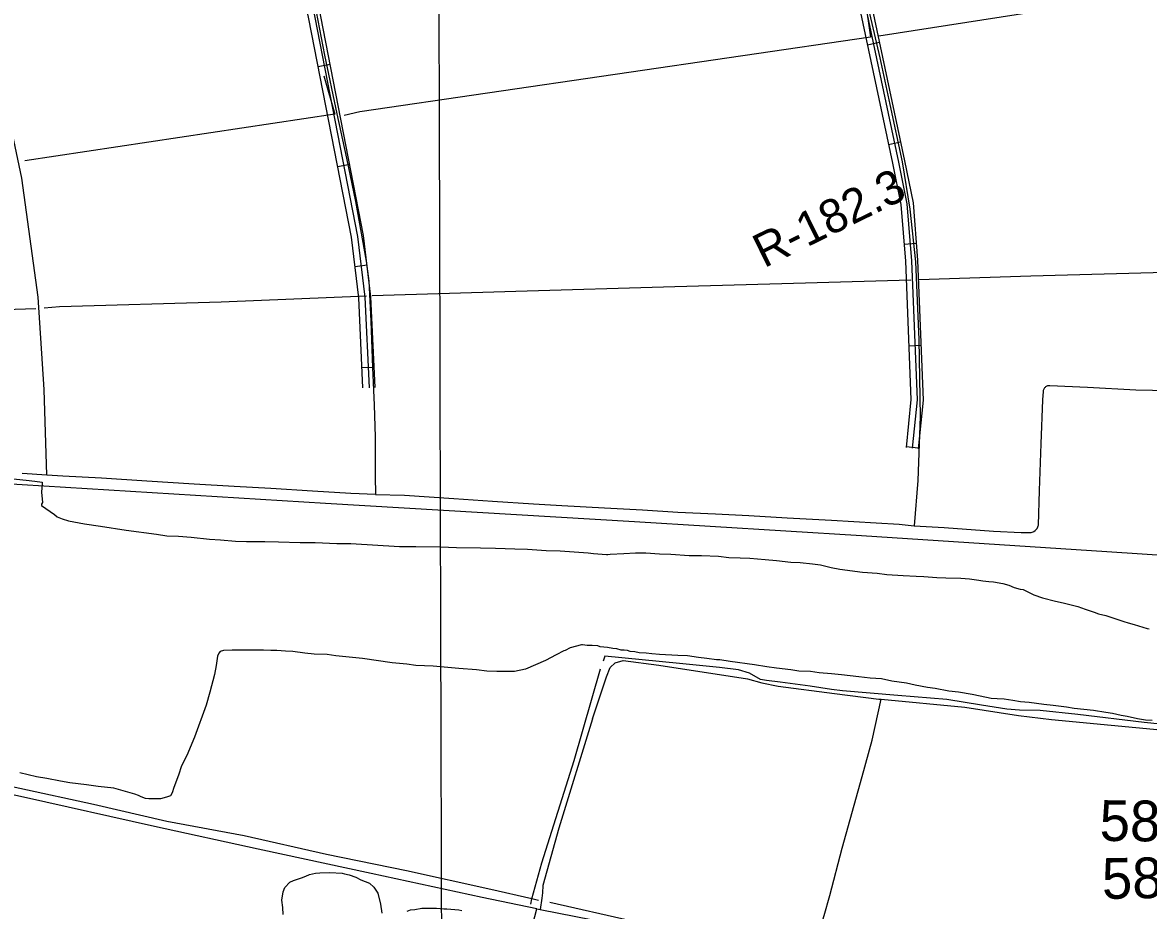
# Model space of a CAD drawing. Extents: x 3355724 to 3393621, y 594744 to 620174.
# Drawn here: x 3379882 to 3382643, y 602888 to 605066 of the extents above; entities that cross this region are included whole.
import ezdxf

# ---------------------------------------------------------------- set-up
doc = ezdxf.new("R2010")
doc.units = 0
for name, color, linetype in [('V-DTCH-CNTR', 7, 'Continuous'), ('V-GRID-MAJR', 7, 'Continuous'), ('V-RIVR-RANG-IDEN', 7, 'Continuous'), ('V-ROAD-CNTR', 7, 'Continuous'), ('V-SITE-VEGE', 7, 'Continuous'), ('V-SURV-IDEN', 7, 'Continuous'), ('V-TOPO-SHOR', 7, 'Continuous')]:
    doc.layers.add(name, color=color, linetype=linetype)

msp = doc.modelspace()

# ---------------------------------------------------------------- linework, layer by layer
at = {"layer": 'V-DTCH-CNTR'}
for points in [[(3381503.5, 606759.2), (3381522.8, 606700.6), (3381548.5, 606624.1), (3381574.1, 606534.7), (3381605.7, 606435.7), (3381639.6, 606329.6), (3381673.5, 606222.8), (3381714.9, 606091.5), (3381734.7, 606022.3), (3381744.1, 605992), (3381747.7, 605980.1), (3381756, 605959.5), (3381785.2, 605861.6), (3381812.4, 605764.8), (3381840.6, 605643.6), (3381868.7, 605519.6), (3381891.4, 605400.3), (3381918.5, 605268.6), (3381953.4, 605112.7), (3381984.3, 604979.8), (3382008.9, 604865.2), (3382038.7, 604724.1)], [(3379941.5, 603955.8), (3379935.5, 604166.2), (3379920.8, 604392.1), (3379880.2, 604684.5), (3379828.6, 604932.5), (3379746.8, 605265), (3379712.7, 605407.2), (3379660.4, 605620), (3379581.1, 605960.3), (3379555.8, 606069.7)], [(3380597.9, 605113.5), (3380622.9, 604986.4), (3380653.1, 604842.2), (3380676.5, 604733.4), (3380698.4, 604626.9), (3380724.7, 604481.1), (3380731.1, 604431.8), (3380735.8, 604333.4), (3380740.6, 604219.8), (3380744.5, 604127.2), (3380746.8, 604049.8), (3380747.2, 603953.4), (3380747.8, 603908.6), (3380687.5, 603911.1), (3380592.9, 603916.5), (3380491.4, 603922.7), (3380401.1, 603927.7), (3380302.7, 603933.9), (3380186.7, 603941.2), (3380075.8, 603948.1), (3379980.9, 603953.2), (3379941.5, 603955.8), (3379881.3, 603959.7)], [(3382038.7, 604724.1), (3382057.9, 604608.3), (3382071.6, 604479.2), (3382079.5, 604288.6), (3382083.4, 604099.6), (3382077.1, 603942.4), (3382068.2, 603831.9)], [(3380747.8, 603908.6), (3380819, 603906.6), (3380939.6, 603898.6), (3381034.2, 603892), (3381134.9, 603885.4), (3381204.2, 603881.4), (3381308.9, 603875.7), (3381402.2, 603871), (3381489, 603865.2), (3381581.6, 603861.3), (3381663.3, 603857), (3381756.7, 603851.5), (3381866, 603845), (3381975.4, 603838.9), (3382031.4, 603835.2), (3382068.2, 603831.9), (3382142.1, 603827.5), (3382263.2, 603818.7), (3382330.9, 603815.5), (3382351.1, 603814.8), (3382353.3, 603815), (3382355.5, 603815.3), (3382359.7, 603816.7), (3382361.6, 603817.6), (3382365.3, 603820.2), (3382368.3, 603823.3), (3382369.6, 603825.1), (3382371.7, 603829), (3382372.4, 603831.1), (3382372.9, 603833.2), (3382375.9, 603918), (3382379.3, 604032.8), (3382383.9, 604140.6), (3382385.4, 604161.2), (3382385.5, 604162.9), (3382385.7, 604164.6), (3382386.2, 604166.3), (3382386.9, 604167.8), (3382387.7, 604169.3), (3382388.7, 604170.7), (3382389.9, 604172), (3382391.2, 604173.1), (3382392.6, 604174.1), (3382394.2, 604174.8), (3382395.8, 604175.4), (3382397.4, 604175.8), (3382399.2, 604176), (3382400.9, 604176), (3382493.5, 604171.4), (3382611.8, 604164.9), (3382735.1, 604162.3)], [(3381279.3, 603358), (3381313.6, 603461.3), (3381323.1, 603483.8), (3381335.5, 603495.2), (3381355.1, 603501.1), (3381442.7, 603489.7), (3381659.4, 603456.2), (3381695.2, 603446.2), (3381734.5, 603438.3), (3381872.6, 603420.5), (3381982, 603406.6), (3381987.7, 603406.1), (3382192.2, 603387), (3382324, 603366.4), (3382404.7, 603356.3), (3382551.1, 603342.2), (3382672.3, 603331.2)], [(3381142.8, 602892.2), (3381008.8, 602919.8), (3380737.1, 602978.4), (3380459.9, 603038.4), (3380205.8, 603093.7), (3379885, 603165.7), (3379586, 603230.3), (3379241.4, 603304.7), (3378950.8, 603368.7), (3378694.7, 603425.1)], [(3381808.8, 602754.1), (3381824.3, 602799.8), (3381847.7, 602875.7), (3381861.8, 602924.9), (3381891.7, 603040.8), (3381941.1, 603216.4), (3381965.1, 603305.6), (3381987.7, 603406.1)], [(3381279.3, 603358), (3381197.5, 603090.3), (3381158.1, 602949.1), (3381157, 602931.5), (3381155.7, 602918.2), (3381151.7, 602890.4)], [(3381114.2, 602782.6), (3381142.8, 602892.2), (3381151.7, 602890.4), (3381451.5, 602831.2)]]:
    msp.add_lwpolyline(points, dxfattribs=at)
at = {"layer": 'V-GRID-MAJR'}
msp.add_spline([(3380917.6, 600183.6), (3380900.8, 606241.7), (3380884.1, 612302.9), (3380867.3, 618364.1), (3380867.3, 618367.2)], degree=3, dxfattribs=at)
at = {"layer": 'V-ROAD-CNTR'}
for p, q in [((3381982.9, 605017), (3381953.5, 605010.8)), ((3380606.9, 604958.1), (3380636.3, 604963.9)), ((3382034.6, 604772.4), (3382005.2, 604766.2)), ((3380654.9, 604712.8), (3380684.4, 604718.6)), ((3382073.5, 604524), (3382043.6, 604521.6)), ((3380697.4, 604467.7), (3380727.2, 604471.3)), ((3382085.1, 604273.6), (3382055.1, 604272.5)), ((3380714.5, 604219.5), (3380744.4, 604220.9)), ((3382078.5, 604022.2), (3382048.6, 604025.2))]:
    msp.add_line(p, q, dxfattribs=at)
for points in [[(3381502, 606748.4), (3381713.6, 606066.2), (3381758.7, 605978), (3381764.3, 605956.2), (3381798.1, 605818.6), (3382029.5, 604723.8), (3382050.7, 604621.5), (3382061.9, 604481.9), (3382075.3, 604140.5), (3382063.4, 604021.8)], [(3380383.6, 606126.5), (3380486.4, 605618.5), (3380598.7, 605078), (3380703.8, 604541.6), (3380721.4, 604392.2), (3380731.8, 604170.3)], [(3381774.4, 605976.9), (3381778.8, 605959.9), (3381812.7, 605821.9), (3382044.2, 604726.9), (3382065.6, 604623.6), (3382076.8, 604482.8), (3382090.3, 604140.1), (3382078.3, 604020.3)], [(3381744.9, 605971.1), (3381749.7, 605952.6), (3381783.4, 605815.2), (3382014.8, 604720.7), (3382035.9, 604619.4), (3382046.9, 604481), (3382060.3, 604141), (3382048.5, 604023.3)], [(3380746.8, 604171), (3380736.4, 604393.5), (3380718.6, 604544), (3380613.4, 605080.9), (3380500.6, 605623.7)], [(3380716.8, 604169.6), (3380706.5, 604391), (3380688.9, 604539.3), (3380584, 605075), (3380471.6, 605615.6)]]:
    msp.add_lwpolyline(points, dxfattribs=at)
at = {"layer": 'V-SITE-VEGE'}
for points in [[(3379852, 603947.9), (3379891.3, 603943.8), (3379912.5, 603940.7), (3379930.6, 603938.6), (3379930.6, 603936.5), (3379928.6, 603914.2), (3379930.8, 603888.7), (3379928.7, 603884.5), (3379928.7, 603881.3), (3379960.7, 603859.1), (3379967, 603853.9), (3379979.8, 603848.6), (3379994.7, 603843.4), (3380034, 603836.1), (3380073.3, 603831), (3380136, 603820.6), (3380210.4, 603811.4), (3380235.9, 603807.2), (3380264.5, 603806.3), (3380295.3, 603803.3), (3380341, 603799.2), (3380367.6, 603797.2), (3380404.7, 603794.2), (3380431.3, 603793.2), (3380475.9, 603793.4), (3380509.9, 603792.5), (3380562.9, 603790.6), (3380600.1, 603790.8), (3380653.2, 603787.8), (3380687.2, 603788), (3380806.1, 603781.1), (3380846.5, 603781.2), (3380907, 603780.4), (3380946.3, 603778.5), (3381004.7, 603777.7), (3381041.8, 603776.8), (3381089.6, 603774.9), (3381120.4, 603773.9), (3381166.1, 603770.9), (3381200.1, 603770), (3381269.1, 603765), (3381281.8, 603764), (3381313.7, 603761), (3381316.9, 603761), (3381323.3, 603762.1), (3381356.2, 603763.3), (3381384.8, 603765.5), (3381410.3, 603765.6), (3381444.3, 603762.6), (3381471.9, 603761.6), (3381516.5, 603758.7), (3381547.3, 603758.8)], [(3381547.3, 603758.8), (3381588.7, 603756.8), (3381614.2, 603753.8), (3381641.8, 603752.8), (3381665.2, 603751.9), (3381703.4, 603748.8), (3381731, 603746.8), (3381766.1, 603742.7), (3381788.4, 603741.8), (3381819.2, 603738.7), (3381838.3, 603735.6), (3381864.9, 603729.4), (3381886.1, 603725.2), (3381941.4, 603718), (3381977.5, 603715), (3382000.9, 603711.9), (3382041.2, 603710), (3382073.1, 603708), (3382092.2, 603707), (3382124, 603705), (3382146.3, 603704.1), (3382182.5, 603703.1), (3382203.7, 603701.1), (3382227.1, 603698), (3382236.6, 603697), (3382251.5, 603695), (3382263.2, 603693.9), (3382285.5, 603689.8), (3382300.4, 603685.6), (3382313.1, 603680.4), (3382328, 603676.2), (3382335.5, 603675.1), (3382341.8, 603672), (3382362.1, 603662.5), (3382383.3, 603655.2), (3382415.2, 603646.8), (3382433.3, 603642.7), (3382469.4, 603633.3), (3382487.5, 603627), (3382509.8, 603619.6), (3382520.5, 603615.4), (3382538.5, 603611.3), (3382550.2, 603607.1), (3382570.4, 603600.8), (3382582.1, 603596.6), (3382592.8, 603593.4), (3382607.6, 603589.3), (3382639.5, 603579.8), (3382644.8, 603578.8)], [(3380366.6, 603523.3), (3380363.5, 603519), (3380360.3, 603511.6), (3380357.2, 603489.3), (3380353.1, 603466.9), (3380341.6, 603423.4), (3380332.2, 603391.5), (3380303.8, 603312.8), (3380284.9, 603268.1), (3380272.3, 603242.6), (3380264.9, 603220.2), (3380253.4, 603189.4), (3380249.2, 603176.6), (3380245, 603169.2), (3380235.5, 603166), (3380220.6, 603161.7), (3380191.9, 603161.5), (3380183.4, 603162.6), (3380172.8, 603166.8), (3380166.4, 603169.9), (3380157.9, 603173.1), (3380129.2, 603181.4), (3380105.8, 603187.7), (3380067.6, 603191.8), (3380038.9, 603195.9), (3379998.5, 603201), (3379975.2, 603205.2), (3379942.2, 603211.4), (3379916.7, 603215.5), (3379875.3, 603226)], [(3382652.2, 603353.8), (3382635.2, 603354.7), (3382616.1, 603357.8), (3382590.6, 603364.1), (3382575.7, 603366.2), (3382554.4, 603371.4), (3382538.5, 603373.4), (3382507.7, 603378.6), (3382460.9, 603383.7), (3382441.8, 603386.8), (3382408.9, 603390.9), (3382386.6, 603392.9), (3382350.5, 603398.1), (3382329.2, 603400.1), (3382310.1, 603403.2), (3382288.8, 603406.3), (3382271.9, 603407.3), (3382257, 603408.3), (3382230.4, 603413.5), (3382210.2, 603417.7), (3382177.3, 603423.9), (3382152.9, 603425.9), (3382119.9, 603432.1), (3382100.8, 603435.2), (3382071, 603440.4), (3382049.8, 603445.6), (3382013.7, 603450.8), (3381988.2, 603456), (3381960.6, 603458), (3381932.9, 603461.1), (3381890.4, 603466.2), (3381866, 603468.2), (3381835.2, 603471.2), (3381814, 603474.3), (3381785.3, 603475.3), (3381766.2, 603478.4), (3381731.1, 603482.5), (3381706.7, 603485.6), (3381676.9, 603490.7), (3381658.9, 603492.8), (3381635.5, 603495.9), (3381617.4, 603499), (3381591.9, 603503.1), (3381583.4, 603503.1), (3381560.1, 603506.2), (3381539.9, 603508.2), (3381512.3, 603512.3), (3381488.9, 603513.3), (3381444.3, 603516.3), (3381425.2, 603517.2), (3381411.4, 603519.3), (3381394.4, 603520.3), (3381383.8, 603522.4), (3381372.1, 603523.4), (3381365.7, 603525.5), (3381357.2, 603526.5), (3381349.8, 603526.5), (3381339.1, 603529.6), (3381329.6, 603530.6), (3381316.8, 603532.7), (3381298.8, 603534.7), (3381292.4, 603536.8), (3381278.6, 603537.8), (3381266.9, 603537.8), (3381255.2, 603539.9), (3381253.1, 603539.9), (3381224.5, 603532.3), (3381212.8, 603525.9), (3381209.6, 603524.8), (3381190.6, 603515.2), (3381164.1, 603501.3), (3381115.3, 603479.8), (3381088.8, 603474.4), (3381045.3, 603474.2), (3381020.9, 603475.2), (3380995.4, 603478.2), (3380951.8, 603481.2), (3380925.3, 603484.3), (3380889.1, 603487.3), (3380846.7, 603489.3), (3380824.4, 603492.3), (3380788.2, 603495.4), (3380716, 603505.7), (3380650.1, 603512.8), (3380628.9, 603515.9), (3380597, 603516.8), (3380574.7, 603518.9), (3380545, 603523), (3380526.9, 603524), (3380505.7, 603526), (3380490.8, 603525.9), (3380472.8, 603526.9), (3380396.3, 603526.6), (3380375.1, 603525.4), (3380366.6, 603523.3)], [(3380521.2, 602878.4), (3380520.1, 602895.4), (3380517.9, 602913.4), (3380521, 602933.6), (3380525.2, 602944.3), (3380537.9, 602957.1), (3380546.4, 602961.3), (3380566.5, 602967.8), (3380577.1, 602972.1)], [(3380577.1, 602972.1), (3380585.6, 602976.4), (3380600.4, 602979.6), (3380611, 602980.7), (3380635.5, 602980.8), (3380666.3, 602979.9), (3380671.6, 602977.8), (3380683.3, 602975.7), (3380699.2, 602969.4), (3380712, 602963.1), (3380733.3, 602954.7), (3380743.9, 602945.2), (3380753.5, 602930.4), (3380760, 602903.9), (3380763.3, 602881.6)], [(3380824.9, 602886.1), (3380833.3, 602889.3), (3380844, 602890.4), (3380860.9, 602893.7), (3380897, 602893.8), (3380915.1, 602891.8), (3380922.5, 602891.8), (3380952.3, 602889.8), (3380959.7, 602887.8)]]:
    msp.add_lwpolyline(points, dxfattribs=at)
at = {"layer": 'V-TOPO-SHOR'}
msp.add_line((3381128.4, 602903.7), (3381130.8, 602916.3), dxfattribs=at)
for points in [[(3383156.7, 605227.5), (3383038.9, 605197.8), (3381981.7, 605033)], [(3381949.1, 605115.4), (3381961.1, 605030), (3380709.5, 604847), (3380671.2, 604838)], [(3380620.9, 604935.1), (3380647.6, 604840.9), (3379887.9, 604727)], [(3383382.6, 604479.8), (3383328.7, 604476.1), (3383078.9, 604471.6), (3382744.4, 604454.8), (3382354.2, 604443.7), (3382079.6, 604434.8)], [(3382059.9, 604433.8), (3381801.5, 604426.7), (3381481.5, 604417.6), (3381091.4, 604406.5), (3380739.7, 604395.6)], [(3380725.2, 604394.7), (3380369.3, 604380.3), (3379973.2, 604368.3), (3379935.5, 604365.6)], [(3379915, 604363.8), (3379583, 604352.9), (3379229.7, 604337.7), (3378804.5, 604323.9), (3378613.7, 604317.1)], [(3383444.9, 603708.1), (3382540.3, 603767.6), (3381939.2, 603807.3), (3381382.4, 603841.2), (3380625.1, 603886.3), (3379296.2, 603968.3), (3378382.8, 604016)], [(3382735.8, 603338.7), (3382632.1, 603349.1), (3382469.4, 603368.9), (3382377.5, 603378.6), (3382326.5, 603379.5), (3382295.1, 603381.4), (3382233.7, 603391.6), (3382148, 603405.3), (3382027.9, 603415.5), (3381892.8, 603427), (3381865.3, 603429.8), (3381813.4, 603438.5), (3381739.5, 603447.7), (3381706.5, 603452), (3381691.6, 603454.9), (3381664.7, 603470.2), (3381637.9, 603478.5), (3381590.8, 603484.2), (3381493.3, 603493.8), (3381309.5, 603511.8), (3381305.8, 603499.2)], [(3381130.8, 602916.3), (3381155.5, 603005.2), (3381234.5, 603255.8), (3381298.9, 603481)], [(3381147.4, 602912.5), (3381130.8, 602916.3), (3381030.2, 602939.1), (3380824, 602985), (3380627.3, 603025.5), (3380425.9, 603070.7), (3380236.3, 603106.6), (3380056.1, 603148.1), (3379875.9, 603187.2), (3379706.8, 603223.4), (3379526.6, 603263.4), (3379315.7, 603306.8), (3379170.1, 603342.5), (3378972.6, 603386.1), (3378745.9, 603434.4)], [(3381802.9, 602771.4), (3381599.1, 602815.8), (3381377.2, 602862.2), (3381175, 602907.3)]]:
    msp.add_lwpolyline(points, dxfattribs=at)

# ---------------------------------------------------------------- texts
at = {"layer": 'V-RIVR-RANG-IDEN'}
msp.add_text('R-182.3', height=83, rotation=26.16, dxfattribs=at).set_placement((3381700.2, 604462.8))
at = {"layer": 'V-SURV-IDEN'}
for s, rotation, p in [('5876+87.8', 359.3967, (3382522.7, 603058.8)), ('5877+90.5', 1.0228, (3382529.4, 602916.1))]:
    msp.add_text(s, height=100, rotation=rotation, dxfattribs=at).set_placement(p)

doc.saveas('drawing.dxf')
